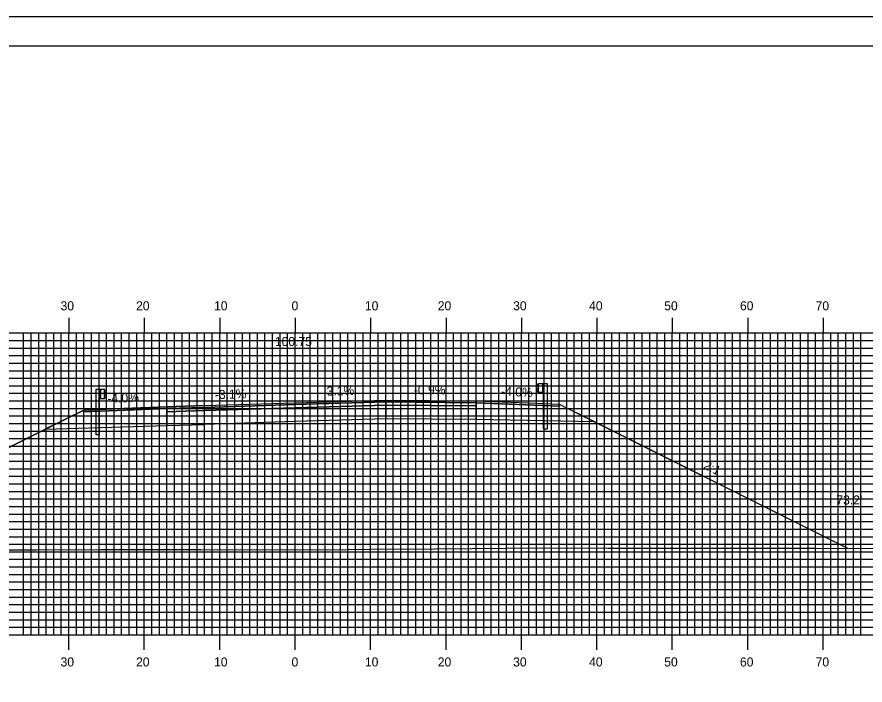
# Model space of a CAD drawing. Extents: x 1758643 to 1758986, y 442591 to 442811.
# Drawn here: x 1758771.8 to 1758884.2, y 442722 to 442810.5 of the extents above; entities that cross this region are included whole.
import ezdxf

# ---------------------------------------------------------------- set-up
doc = ezdxf.new("R2010")
doc.units = 0
for name, color, linetype in [('ANNOTATION', 7, 'Continuous'), ('BORDER', 7, 'Continuous'), ('D_Guardrail_Beam_Lt', 7, 'Continuous'), ('D_Guardrail_Beam_Rt', 7, 'Continuous'), ('D_Roadway_Centerline', 7, 'Continuous'), ('D_Roadway_Centerline_Text', 7, 'Continuous'), ('D_Roadway_Edge_Shoulder', 7, 'Continuous'), ('D_Roadway_Edge_TW', 7, 'Continuous'), ('D_Roadway_Pavement', 7, 'Continuous'), ('D_Roadway_SlopeLines', 7, 'Continuous'), ('D_Roadway_SubGrade', 7, 'Continuous'), ('D_Text_Standard', 7, 'Continuous'), ('H_V ANNOTATION', 7, 'Continuous'), ('MAJOR', 7, 'Continuous'), ('MINOR', 7, 'Continuous'), ('PLOT BOUNDARY', 7, 'Continuous'), ('S_Roadway_Centerline', 7, 'Continuous')]:
    doc.layers.add(name, color=color, linetype=linetype)

msp = doc.modelspace()

# ---------------------------------------------------------------- linework, layer by layer
at = {"layer": 'BORDER'}
msp.add_lwpolyline([(1758659.05, 442596.67), (1758979.05, 442596.67), (1758979.05, 442806.67), (1758659.05, 442806.67)], close=True, dxfattribs=at)
at = {"layer": 'D_Guardrail_Beam_Lt'}
for p, q in [((1758782.21, 442761.16), (1758782.21, 442755.16)), ((1758782.68, 442761.16), (1758782.21, 442761.16)), ((1758783.36, 442761.16), (1758782.68, 442761.16)), ((1758782.68, 442761.16), (1758782.68, 442759.99)), ((1758782.74, 442761.16), (1758782.74, 442759.99)), ((1758782.84, 442761.16), (1758782.84, 442759.99)), ((1758783.36, 442759.99), (1758783.36, 442761.16)), ((1758783.36, 442761.07), (1758783.44, 442761.06)), ((1758783.37, 442760.61), (1758783.37, 442760.54)), ((1758783.6, 442760.81), (1758783.4, 442760.67)), ((1758783.4, 442760.47), (1758783.6, 442760.34)), ((1758783.45, 442761.05), (1758783.6, 442760.95)), ((1758782.68, 442759.99), (1758783.36, 442759.99)), ((1758782.7, 442755.16), (1758782.7, 442759.99)), ((1758783.44, 442760.09), (1758783.36, 442760.07)), ((1758783.6, 442760.19), (1758783.45, 442760.09)), ((1758782.7, 442755.16), (1758782.21, 442755.16))]:
    msp.add_line(p, q, dxfattribs=at)
for centre, major_axis, start_param, end_param in [((1758783.45, 442760.61), (-0.0789, 0), 5.323254, 6.283185), ((1758783.45, 442760.54), (-0.0789, 0), 6.283185, 7.243116), ((1758783.43, 442761.02), (0.0417, 0), 0.959931, 1.376053), ((1758783.55, 442760.88), (0.0877, 0), 5.323254, 7.243116), ((1758783.43, 442760.13), (0.0417, 0), 4.907132, 5.323254), ((1758783.55, 442760.26), (0.0877, 0), 5.323254, 7.243116)]:
    msp.add_ellipse(centre, major_axis=major_axis, ratio=0.995501, start_param=start_param, end_param=end_param, dxfattribs=at)
at = {"layer": 'D_Guardrail_Beam_Rt'}
for p, q in [((1758840.83, 442761.84), (1758840.69, 442761.74)), ((1758840.69, 442761.6), (1758840.88, 442761.46)), ((1758840.92, 442761.86), (1758840.85, 442761.85)), ((1758840.92, 442761.95), (1758841.61, 442761.95)), ((1758840.92, 442760.78), (1758840.92, 442761.95)), ((1758841.44, 442761.95), (1758841.44, 442760.78)), ((1758841.54, 442761.95), (1758841.54, 442760.78)), ((1758841.61, 442761.95), (1758842.08, 442761.95)), ((1758841.61, 442761.95), (1758841.61, 442760.78)), ((1758842.08, 442761.95), (1758842.08, 442755.95)), ((1758840.88, 442761.26), (1758840.69, 442761.13)), ((1758840.69, 442760.98), (1758840.83, 442760.88)), ((1758840.85, 442760.88), (1758840.92, 442760.86)), ((1758840.91, 442761.4), (1758840.91, 442761.33)), ((1758841.61, 442760.78), (1758840.92, 442760.78)), ((1758841.59, 442755.95), (1758841.59, 442760.78)), ((1758841.59, 442755.95), (1758842.08, 442755.95))]:
    msp.add_line(p, q, dxfattribs=at)
for centre, major_axis, start_param, end_param in [((1758840.74, 442761.67), (-0.0877, 0), 5.323254, 7.243116), ((1758840.85, 442761.81), (-0.0417, 0), 4.907132, 5.323254), ((1758840.74, 442761.06), (-0.0877, 0), 5.323254, 7.243116), ((1758840.85, 442760.92), (-0.0417, 0), 0.959931, 1.376053), ((1758840.84, 442761.4), (0.0789, 0), 0, 0.959931), ((1758840.84, 442761.33), (0.0789, 0), 5.323254, 6.283185)]:
    msp.add_ellipse(centre, major_axis=major_axis, ratio=0.995501, start_param=start_param, end_param=end_param, dxfattribs=at)
at = {"layer": 'D_Roadway_Centerline'}
msp.add_lwpolyline([(1758743.18, 442739.72), (1758775.52, 442755.9), (1758780.64, 442758.45), (1758783.64, 442758.57), (1758791.64, 442758.89), (1758796.65, 442759.05), (1758808.65, 442759.42), (1758820.65, 442759.78), (1758832.65, 442759.68), (1758840.65, 442759.36), (1758843.65, 442759.24), (1758848.4, 442756.87), (1758881.86, 442740.14)], dxfattribs=at)
at = {"layer": 'D_Roadway_Edge_Shoulder'}
for points in [[(1758832.65, 442759.68), (1758840.65, 442759.36), (1758840.65, 442759.36), (1758843.65, 442759.24), (1758843.65, 442758.99), (1758832.65, 442759.43)], [(1758791.64, 442758.89), (1758783.64, 442758.57), (1758783.64, 442758.57), (1758780.64, 442758.45), (1758780.64, 442758.2), (1758791.64, 442758.64)]]:
    msp.add_lwpolyline(points, close=True, dxfattribs=at)
at = {"layer": 'D_Roadway_Edge_TW'}
for points in [[(1758796.65, 442758.8), (1758796.65, 442759.05), (1758808.65, 442759.42), (1758820.65, 442759.78), (1758820.65, 442759.53), (1758808.65, 442759.17)], [(1758820.65, 442759.78), (1758832.65, 442759.68), (1758832.65, 442759.43), (1758820.65, 442759.53)], [(1758796.65, 442759.05), (1758791.64, 442758.89), (1758791.64, 442758.64), (1758796.65, 442758.8)]]:
    msp.add_lwpolyline(points, close=True, dxfattribs=at)
at = {"layer": 'D_Roadway_Pavement'}
for points in [[(1758796.65, 442758.38), (1758796.65, 442758.8), (1758808.65, 442759.17), (1758820.65, 442759.53), (1758820.65, 442759.12), (1758808.65, 442758.75)], [(1758820.65, 442759.53), (1758832.65, 442759.43), (1758832.65, 442759.02), (1758820.65, 442759.12)], [(1758796.65, 442758.8), (1758791.64, 442758.64), (1758791.64, 442758.22), (1758796.65, 442758.38)]]:
    msp.add_lwpolyline(points, close=True, dxfattribs=at)
for points in [[(1758832.65, 442759.43), (1758832.65, 442759.02)], [(1758832.65, 442759.43), (1758832.65, 442759.02)], [(1758832.65, 442759.43), (1758832.65, 442759.02)], [(1758832.65, 442759.43), (1758832.65, 442759.02)], [(1758791.64, 442758.64), (1758791.64, 442758.22)], [(1758791.64, 442758.64), (1758791.64, 442758.22)]]:
    msp.add_lwpolyline(points, dxfattribs=at)
at = {"layer": 'D_Roadway_SlopeLines'}
for points in [[(1758843.65, 442759.24), (1758881.86, 442740.14)], [(1758780.64, 442758.45), (1758743.18, 442739.72)]]:
    msp.add_lwpolyline(points, dxfattribs=at)
at = {"layer": 'D_Roadway_SubGrade'}
for points in [[(1758832.65, 442759.02), (1758832.65, 442759.43), (1758843.65, 442758.99), (1758843.65, 442759.24), (1758848.4, 442756.87), (1758832.65, 442757.18)], [(1758791.64, 442758.22), (1758791.64, 442758.64), (1758780.64, 442758.2), (1758780.64, 442758.45), (1758775.52, 442755.9), (1758791.64, 442756.39)], [(1758796.65, 442758.38), (1758791.64, 442758.22), (1758791.64, 442756.39), (1758796.65, 442756.55)], [(1758796.65, 442756.55), (1758796.65, 442758.38), (1758808.65, 442758.75), (1758820.65, 442759.12), (1758820.65, 442757.28), (1758808.65, 442756.92)], [(1758820.65, 442759.12), (1758832.65, 442759.02), (1758832.65, 442757.18), (1758820.65, 442757.28)]]:
    msp.add_lwpolyline(points, close=True, dxfattribs=at)
at = {"layer": 'MAJOR'}
for p, q in [((1758778.65, 442770.67), (1758778.65, 442768.67)), ((1758788.65, 442770.67), (1758788.65, 442768.67)), ((1758798.65, 442770.67), (1758798.65, 442768.67)), ((1758808.65, 442770.67), (1758808.65, 442768.67)), ((1758818.65, 442770.67), (1758818.65, 442768.67)), ((1758828.65, 442770.67), (1758828.65, 442768.67)), ((1758838.65, 442770.67), (1758838.65, 442768.67)), ((1758848.65, 442770.67), (1758848.65, 442768.67)), ((1758858.65, 442770.67), (1758858.65, 442768.67)), ((1758868.65, 442770.67), (1758868.65, 442768.67)), ((1758878.65, 442770.67), (1758878.65, 442768.67)), ((1758668.65, 442768.67), (1758948.65, 442768.67)), ((1758668.65, 442768.67), (1758948.65, 442768.67)), ((1758778.65, 442728.67), (1758778.65, 442768.67)), ((1758788.65, 442728.67), (1758788.65, 442768.67)), ((1758798.65, 442728.67), (1758798.65, 442768.67)), ((1758808.65, 442728.67), (1758808.65, 442768.67)), ((1758818.65, 442728.67), (1758818.65, 442768.67)), ((1758828.65, 442728.67), (1758828.65, 442768.67)), ((1758838.65, 442728.67), (1758838.65, 442768.67)), ((1758848.65, 442728.67), (1758848.65, 442768.67)), ((1758858.65, 442728.67), (1758858.65, 442768.67)), ((1758868.65, 442728.67), (1758868.65, 442768.67)), ((1758878.65, 442728.67), (1758878.65, 442768.67)), ((1758668.65, 442763.67), (1758948.65, 442763.67)), ((1758668.65, 442758.67), (1758948.65, 442758.67)), ((1758668.65, 442753.67), (1758948.65, 442753.67)), ((1758668.65, 442748.67), (1758948.65, 442748.67)), ((1758668.65, 442743.67), (1758948.65, 442743.67)), ((1758668.65, 442738.67), (1758948.65, 442738.67)), ((1758668.65, 442733.67), (1758948.65, 442733.67)), ((1758668.65, 442728.67), (1758948.65, 442728.67)), ((1758668.65, 442728.67), (1758948.65, 442728.67)), ((1758778.65, 442726.66), (1758778.65, 442728.67)), ((1758788.65, 442726.66), (1758788.65, 442728.67)), ((1758798.65, 442726.66), (1758798.65, 442728.67)), ((1758808.65, 442726.66), (1758808.65, 442728.67)), ((1758818.65, 442726.66), (1758818.65, 442728.67)), ((1758828.65, 442726.66), (1758828.65, 442728.67)), ((1758838.65, 442726.66), (1758838.65, 442728.67)), ((1758848.65, 442726.66), (1758848.65, 442728.67)), ((1758858.65, 442726.66), (1758858.65, 442728.67)), ((1758868.65, 442726.66), (1758868.65, 442728.67)), ((1758878.65, 442726.66), (1758878.65, 442728.67))]:
    msp.add_line(p, q, dxfattribs=at)
at = {"layer": 'MINOR'}
for p, q in [((1758772.65, 442728.67), (1758772.65, 442768.67)), ((1758773.65, 442728.67), (1758773.65, 442768.67)), ((1758774.65, 442728.67), (1758774.65, 442768.67)), ((1758775.65, 442728.67), (1758775.65, 442768.67)), ((1758776.65, 442728.67), (1758776.65, 442768.67)), ((1758777.65, 442728.67), (1758777.65, 442768.67)), ((1758779.65, 442728.67), (1758779.65, 442768.67)), ((1758780.65, 442728.67), (1758780.65, 442768.67)), ((1758781.65, 442728.67), (1758781.65, 442768.67)), ((1758782.65, 442728.67), (1758782.65, 442768.67)), ((1758783.65, 442728.67), (1758783.65, 442768.67)), ((1758784.65, 442728.67), (1758784.65, 442768.67)), ((1758785.65, 442728.67), (1758785.65, 442768.67)), ((1758786.65, 442728.67), (1758786.65, 442768.67)), ((1758787.65, 442728.67), (1758787.65, 442768.67)), ((1758789.65, 442728.67), (1758789.65, 442768.67)), ((1758790.65, 442728.67), (1758790.65, 442768.67)), ((1758791.65, 442728.67), (1758791.65, 442768.67)), ((1758792.65, 442728.67), (1758792.65, 442768.67)), ((1758793.65, 442728.67), (1758793.65, 442768.67)), ((1758794.65, 442728.67), (1758794.65, 442768.67)), ((1758795.65, 442728.67), (1758795.65, 442768.67)), ((1758796.65, 442728.67), (1758796.65, 442768.67)), ((1758797.65, 442728.67), (1758797.65, 442768.67)), ((1758799.65, 442728.67), (1758799.65, 442768.67)), ((1758800.65, 442728.67), (1758800.65, 442768.67)), ((1758801.65, 442728.67), (1758801.65, 442768.67)), ((1758802.65, 442728.67), (1758802.65, 442768.67)), ((1758803.65, 442728.67), (1758803.65, 442768.67)), ((1758804.65, 442728.67), (1758804.65, 442768.67)), ((1758805.65, 442728.67), (1758805.65, 442768.67)), ((1758806.65, 442728.67), (1758806.65, 442768.67)), ((1758807.65, 442728.67), (1758807.65, 442768.67)), ((1758809.65, 442728.67), (1758809.65, 442768.67)), ((1758810.65, 442728.67), (1758810.65, 442768.67)), ((1758811.65, 442728.67), (1758811.65, 442768.67)), ((1758812.65, 442728.67), (1758812.65, 442768.67)), ((1758813.65, 442728.67), (1758813.65, 442768.67)), ((1758814.65, 442728.67), (1758814.65, 442768.67)), ((1758815.65, 442728.67), (1758815.65, 442768.67)), ((1758816.65, 442728.67), (1758816.65, 442768.67)), ((1758817.65, 442728.67), (1758817.65, 442768.67)), ((1758819.65, 442728.67), (1758819.65, 442768.67)), ((1758820.65, 442728.67), (1758820.65, 442768.67)), ((1758821.65, 442728.67), (1758821.65, 442768.67)), ((1758822.65, 442728.67), (1758822.65, 442768.67)), ((1758823.65, 442728.67), (1758823.65, 442768.67)), ((1758824.65, 442728.67), (1758824.65, 442768.67)), ((1758825.65, 442728.67), (1758825.65, 442768.67)), ((1758826.65, 442728.67), (1758826.65, 442768.67)), ((1758827.65, 442728.67), (1758827.65, 442768.67)), ((1758829.65, 442728.67), (1758829.65, 442768.67)), ((1758830.65, 442728.67), (1758830.65, 442768.67)), ((1758831.65, 442728.67), (1758831.65, 442768.67)), ((1758832.65, 442728.67), (1758832.65, 442768.67)), ((1758833.65, 442728.67), (1758833.65, 442768.67)), ((1758834.65, 442728.67), (1758834.65, 442768.67)), ((1758835.65, 442728.67), (1758835.65, 442768.67)), ((1758836.65, 442728.67), (1758836.65, 442768.67)), ((1758837.65, 442728.67), (1758837.65, 442768.67)), ((1758839.65, 442728.67), (1758839.65, 442768.67)), ((1758840.65, 442728.67), (1758840.65, 442768.67)), ((1758841.65, 442728.67), (1758841.65, 442768.67)), ((1758842.65, 442728.67), (1758842.65, 442768.67)), ((1758843.65, 442728.67), (1758843.65, 442768.67)), ((1758844.65, 442728.67), (1758844.65, 442768.67)), ((1758845.65, 442728.67), (1758845.65, 442768.67)), ((1758846.65, 442728.67), (1758846.65, 442768.67)), ((1758847.65, 442728.67), (1758847.65, 442768.67)), ((1758849.65, 442728.67), (1758849.65, 442768.67)), ((1758850.65, 442728.67), (1758850.65, 442768.67)), ((1758851.65, 442728.67), (1758851.65, 442768.67)), ((1758852.65, 442728.67), (1758852.65, 442768.67)), ((1758853.65, 442728.67), (1758853.65, 442768.67)), ((1758854.65, 442728.67), (1758854.65, 442768.67)), ((1758855.65, 442728.67), (1758855.65, 442768.67)), ((1758856.65, 442728.67), (1758856.65, 442768.67)), ((1758857.65, 442728.67), (1758857.65, 442768.67)), ((1758859.65, 442728.67), (1758859.65, 442768.67)), ((1758860.65, 442728.67), (1758860.65, 442768.67)), ((1758861.65, 442728.67), (1758861.65, 442768.67)), ((1758862.65, 442728.67), (1758862.65, 442768.67)), ((1758863.65, 442728.67), (1758863.65, 442768.67)), ((1758864.65, 442728.67), (1758864.65, 442768.67)), ((1758865.65, 442728.67), (1758865.65, 442768.67)), ((1758866.65, 442728.67), (1758866.65, 442768.67)), ((1758867.65, 442728.67), (1758867.65, 442768.67)), ((1758869.65, 442728.67), (1758869.65, 442768.67)), ((1758870.65, 442728.67), (1758870.65, 442768.67)), ((1758871.65, 442728.67), (1758871.65, 442768.67)), ((1758872.65, 442728.67), (1758872.65, 442768.67)), ((1758873.65, 442728.67), (1758873.65, 442768.67)), ((1758874.65, 442728.67), (1758874.65, 442768.67)), ((1758875.65, 442728.67), (1758875.65, 442768.67)), ((1758876.65, 442728.67), (1758876.65, 442768.67)), ((1758877.65, 442728.67), (1758877.65, 442768.67)), ((1758879.65, 442728.67), (1758879.65, 442768.67)), ((1758880.65, 442728.67), (1758880.65, 442768.67)), ((1758881.65, 442728.67), (1758881.65, 442768.67)), ((1758882.65, 442728.67), (1758882.65, 442768.67)), ((1758883.65, 442728.67), (1758883.65, 442768.67)), ((1758668.65, 442767.67), (1758948.65, 442767.67)), ((1758668.65, 442766.67), (1758948.65, 442766.67)), ((1758668.65, 442765.67), (1758948.65, 442765.67)), ((1758668.65, 442764.67), (1758948.65, 442764.67)), ((1758668.65, 442762.67), (1758948.65, 442762.67)), ((1758668.65, 442761.67), (1758948.65, 442761.67)), ((1758668.65, 442760.67), (1758948.65, 442760.67)), ((1758668.65, 442759.67), (1758948.65, 442759.67)), ((1758668.65, 442757.67), (1758948.65, 442757.67)), ((1758668.65, 442756.67), (1758948.65, 442756.67)), ((1758668.65, 442755.67), (1758948.65, 442755.67)), ((1758668.65, 442754.67), (1758948.65, 442754.67)), ((1758668.65, 442752.67), (1758948.65, 442752.67)), ((1758668.65, 442751.67), (1758948.65, 442751.67)), ((1758668.65, 442750.67), (1758948.65, 442750.67)), ((1758668.65, 442749.67), (1758948.65, 442749.67)), ((1758668.65, 442747.67), (1758948.65, 442747.67)), ((1758668.65, 442746.67), (1758948.65, 442746.67)), ((1758668.65, 442745.67), (1758948.65, 442745.67)), ((1758668.65, 442744.67), (1758948.65, 442744.67)), ((1758668.65, 442742.67), (1758948.65, 442742.67)), ((1758668.65, 442741.67), (1758948.65, 442741.67)), ((1758668.65, 442740.67), (1758948.65, 442740.67)), ((1758668.65, 442739.67), (1758948.65, 442739.67)), ((1758668.65, 442737.67), (1758948.65, 442737.67)), ((1758668.65, 442736.67), (1758948.65, 442736.67)), ((1758668.65, 442735.67), (1758948.65, 442735.67)), ((1758668.65, 442734.67), (1758948.65, 442734.67)), ((1758668.65, 442732.67), (1758948.65, 442732.67)), ((1758668.65, 442731.67), (1758948.65, 442731.67)), ((1758668.65, 442730.67), (1758948.65, 442730.67)), ((1758668.65, 442729.67), (1758948.65, 442729.67))]:
    msp.add_line(p, q, dxfattribs=at)
at = {"layer": 'PLOT BOUNDARY'}
msp.add_lwpolyline([(1758642.86, 442590.55), (1758982.86, 442590.55), (1758982.86, 442810.55), (1758642.86, 442810.55)], close=True, dxfattribs=at)
at = {"layer": 'S_Roadway_Centerline'}
msp.add_lwpolyline([(1758764.54, 442739.94), (1758774.35, 442739.95), (1758782.88, 442739.98), (1758793.47, 442739.98), (1758796.13, 442739.98), (1758812.93, 442739.92), (1758818.52, 442740.01), (1758827.16, 442740.08), (1758832.11, 442740.12), (1758841.23, 442740.18), (1758850.14, 442740.14), (1758859.2, 442740.13), (1758877.44, 442740.14), (1758893.25, 442740.12)], dxfattribs=at)

# ---------------------------------------------------------------- texts
at = {"layer": 'ANNOTATION'}
for s, rotation, p in [('3.1%', 1.7625, (1758812.84, 442760.35)), ('-0.9%', 359.5122, (1758824.38, 442760.55)), ('-4.0%', 357.7094, (1758835.94, 442760.35)), ('-4.0%', 2.2906, (1758783.77, 442759.38)), ('-3.1%', 1.7625, (1758798.02, 442759.89)), ('2:1', 333.4349, (1758862.69, 442750.76))]:
    msp.add_text(s, height=1.2, rotation=rotation, dxfattribs=at).set_placement(p)
at = {"layer": 'D_Roadway_Centerline'}
for s, p in [('C', (1758808.64, 442759.42)), ('L', (1758808.65, 442759.41))]:
    msp.add_text(s, height=0.0146, dxfattribs=at).set_placement(p)
at = {"layer": 'D_Roadway_Centerline_Text'}
msp.add_text('100.75', height=1.2, dxfattribs=at).set_placement((1758805.97, 442766.94))
at = {"layer": 'D_Text_Standard'}
msp.add_text("73.2'", height=1.2, dxfattribs=at).set_placement((1758880.4, 442745.94))
at = {"layer": 'H_V ANNOTATION'}
for s, p in [('30', (1758777.55, 442771.67)), ('20', (1758787.56, 442771.67)), ('10', (1758797.9, 442771.67)), ('0', (1758808.17, 442771.67)), ('10', (1758817.9, 442771.67)), ('20', (1758827.56, 442771.67)), ('30', (1758837.55, 442771.67)), ('40', (1758847.62, 442771.67)), ('50', (1758857.58, 442771.67)), ('60', (1758867.62, 442771.67)), ('70', (1758877.65, 442771.67)), ('30', (1758777.55, 442724.47)), ('20', (1758787.56, 442724.47)), ('10', (1758797.9, 442724.47)), ('0', (1758808.17, 442724.47)), ('10', (1758817.9, 442724.47)), ('20', (1758827.56, 442724.47)), ('30', (1758837.55, 442724.47)), ('40', (1758847.62, 442724.47)), ('50', (1758857.58, 442724.47)), ('60', (1758867.62, 442724.47)), ('70', (1758877.65, 442724.47))]:
    msp.add_text(s, height=1.2, dxfattribs=at).set_placement(p)

doc.saveas('drawing.dxf')
